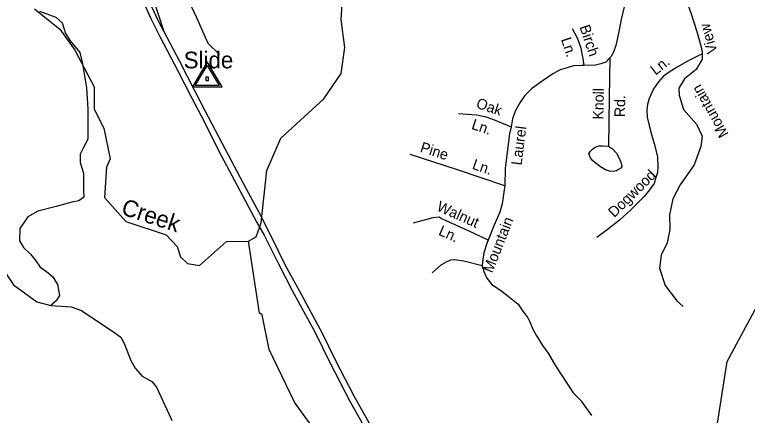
# Model space of a CAD drawing. Extents: x 990631 to 1056237, y 535999 to 585651.
# Drawn here: x 1042549 to 1049136, y 551391 to 554992 of the extents above; entities that cross this region are included whole.
import ezdxf

# ---------------------------------------------------------------- set-up
doc = ezdxf.new("R2010")
doc.units = 0
for name, color, linetype in [('Exist Hydrographic Creek Single Shore', 7, 'Continuous'), ('Exist Hydrographic Creek Single Shore Label', 7, 'Continuous'), ('Exist Road Non-System Type 51', 7, 'Continuous'), ('Exist Road Non-System Type 51 Label', 7, 'Continuous'), ('Exist Road Primary Interstate Divided Center Attributed', 7, 'Continuous'), ('Exist Road Primary Interstate Ramp 1 Lane Attributed', 7, 'Continuous'), ('Exist Survey Geodetic Marker CELL', 7, 'Continuous'), ('Exist Survey Geodetic Marker Label', 7, 'Continuous')]:
    doc.layers.add(name, color=color, linetype=linetype)

msp = doc.modelspace()

# ---------------------------------------------------------------- linework, layer by layer
at = {"layer": 'Exist Hydrographic Creek Single Shore'}
for points in [[(1044652.4, 552955.3), (1044720.5, 552996.7), (1044766.1, 553120.5), (1044814.6, 553592.1), (1044940.6, 553881.6), (1045327.2, 554234.9), (1045484.6, 554464.7), (1045517.2, 554697.1), (1045483.5, 554947.2), (1045500.9, 555229.1), (1045581.2, 555527.7)], [(1042726.7, 555045.3), (1042954.2, 554860.3), (1043089.7, 554673.8), (1043262.7, 554342.1), (1043264.4, 554141.8), (1043350.8, 553972.7), (1043408.7, 553695.9), (1043372.9, 553621.1), (1043355.6, 553349.1), (1043549.1, 553131.8), (1043912.2, 553013), (1044008.8, 552909.3), (1044039.2, 552816.8), (1044104, 552756.4), (1044211.7, 552737.8), (1044452.2, 552952.8), (1044652.4, 552955.3)], [(1049445.6, 548500.3), (1049438.6, 548539.9), (1049074.6, 548895.1), (1048962.6, 549041.8), (1048753.5, 549531.7), (1048626.9, 549744.3), (1048588.6, 549843.6), (1048613.7, 550368.2), (1048706.6, 550648.6), (1048756.5, 550923.2), (1048869.5, 551337.8), (1048953.6, 551874.3), (1049308.5, 552530.1), (1049408.5, 553053.3), (1049407.6, 553269.9), (1049534.5, 553858.1), (1049551.5, 553884), (1049619.5, 554181.3)], [(1045564.2, 550006.6), (1045650.1, 550188.5), (1045739.3, 550297.6), (1045779, 550337.3), (1045934.3, 550370.3), (1045997.1, 550446.4), (1045763.4, 550678.3), (1045669.3, 550864), (1045589.4, 550973.9), (1045304.2, 551176.5), (1045064.8, 551509.6), (1044837.9, 551983.4), (1044773.1, 552293.3), (1044748.6, 552310.1), (1044652.4, 552955.3)]]:
    msp.add_lwpolyline(points, dxfattribs=at)
at = {"layer": 'Exist Road Non-System Type 51'}
for points in [[(1047140.8, 557891.9), (1047023.8, 557816.6), (1046885.8, 557666.1), (1046768.8, 557469.5), (1046693.6, 557268.8), (1046551.4, 556863.1), (1046430.2, 556599.7), (1046359.1, 556553.7), (1046254.6, 556570.4), (1046062.3, 556612.2), (1045673.6, 556720.9), (1045427, 556792), (1045289, 556779.5), (1045071.6, 556683.3), (1044917, 556587.1), (1044565.8, 556281.8), (1044361, 556068.6), (1044269.9, 555844.4), (1044127.8, 555656.2), (1044098.5, 555543.3), (1044090.1, 555166.9), (1044182.1, 554966.2), (1044286.6, 554737.4), (1044391.1, 554632.9)], [(1048561.7, 555408.4), (1048543.3, 555399), (1048503.3, 555398.2), (1048435.7, 555410.4), (1048366.2, 555428.8), (1048296.7, 555443), (1048246.9, 555452.6), (1048220.8, 555449.3), (1048193.9, 555424.3), (1048162.4, 555379.3), (1048128.4, 555314.3), (1048085.3, 555217.6), (1048028.1, 555061.3), (1048002.6, 554948.1), (1047978.5, 554824.8), (1047953.1, 554715.4), (1047933.1, 554656), (1047909.6, 554612.7), (1047899.4, 554603.1)], [(1048561.7, 555408.4), (1048574.1, 555300), (1048575.7, 555217.9), (1048579.8, 555165.8), (1048595.7, 555099), (1048626.9, 555010), (1048681.5, 554842.2), (1048717.5, 554710.8), (1048729.6, 554656.6), (1048731.1, 554640.6)], [(1042771.9, 555023.7), (1042918.2, 554969.4), (1042976.7, 554919.2), (1043006, 554823), (1043047.8, 554756.1), (1043134.4, 554650.8), (1043159.5, 554550.5), (1043193, 554333), (1043205.5, 554144.8), (1043205.5, 553873), (1043163.7, 553793.5), (1043138.6, 553739.2), (1043138.6, 553663.9), (1043167.9, 553567.7), (1043167.9, 553502), (1043167.9, 553418.4), (1043172, 553351.5), (1043126.1, 553318), (1043063.4, 553305.5), (1042921.2, 553267.9), (1042758.2, 553226), (1042666.2, 553175.9), (1042595.2, 553071.3), (1042591, 552960.9), (1042628.6, 552898.2), (1042691.3, 552839.6), (1042733.1, 552789.4), (1042779.1, 552722.5), (1042833.5, 552684.9), (1042892, 552634.7), (1042933.8, 552567.8), (1042950.5, 552467.4), (1042921.2, 552421.4), (1042875.3, 552379.6)], [(1047559.7, 554868.2), (1047603.1, 554788.7), (1047619.8, 554744.2), (1047637.9, 554689.6), (1047648.5, 554641.1), (1047657, 554596.8), (1047667, 554536.5)], [(1047899.4, 554603.1), (1047862.3, 554566.2), (1047817.7, 554549.7), (1047771.3, 554539.2), (1047667, 554536.5)], [(1048731.1, 554640.6), (1048604.9, 554576.5), (1048505.2, 554519.7), (1048431.7, 554475.9), (1048380.4, 554435.5), (1048336.9, 554389), (1048292.8, 554326.3), (1048254, 554239.4), (1048238.3, 554185.9), (1048232.7, 554136.2), (1048236.6, 554069.9), (1048252.1, 553995.4), (1048275.5, 553914.7), (1048304.3, 553813.6), (1048327, 553712.7), (1048332.3, 553628.6), (1048326.6, 553572.7), (1048313.1, 553527.2), (1048299.5, 553475.4), (1048255.7, 553418.9), (1048207.7, 553358.4), (1048083.8, 553236.3), (1047986.7, 553145.4), (1047875.9, 553056.8), (1047781.5, 552987.9)], [(1047899.4, 554603.1), (1047894.1, 554249.1), (1047886.1, 553811.1)], [(1048731.1, 554640.6), (1048729.8, 554592.4), (1048675.2, 554499.9), (1048570.1, 554415.8), (1048519.7, 554331.7), (1048523.9, 554268.7), (1048561.7, 554138.4), (1048679.4, 554008.1), (1048729.8, 553898.8), (1048717.2, 553806.3), (1048658.4, 553642.3), (1048532.3, 553461.6), (1048465.1, 553335.5), (1048435.7, 553192.6), (1048439.9, 553062.3), (1048414.6, 552940.4), (1048360, 552831.1), (1048347.4, 552713.4), (1048397.8, 552559.1), (1048502.9, 552420.4), (1048557.5, 552369.9)], [(1047667, 554536.5), (1047647, 554535.1), (1047572.9, 554531.6), (1047516.3, 554515.4), (1047453.7, 554495.2), (1047386.4, 554459.4), (1047290.2, 554394.5), (1047194, 554325.6), (1047136, 554265.3), (1047090.1, 554200.8), (1047049.5, 554124), (1047025.3, 554054.7), (1047011, 553983.1)], [(1046538.5, 554102.5), (1046702.1, 554091.2), (1046775.8, 554076.7), (1046854.9, 554050.1), (1047011, 553983.1)], [(1042136.5, 553923.9), (1042199.2, 553798.4), (1042203.4, 553664.6), (1042182.5, 553493.2), (1042182.5, 553338.4), (1042195, 553271.5), (1042228.5, 553187.9), (1042333, 553029), (1042429.1, 552725.8), (1042537.8, 552562.7), (1042746.8, 552412.1), (1042875.3, 552379.6)], [(1047011, 553983.1), (1046997, 553919.6), (1046972.8, 553732.2), (1046958.9, 553608.7), (1046954, 553454.7)], [(1047886.1, 553811.1), (1047923.2, 553787.7), (1047958, 553746.6), (1047982.5, 553701.9), (1048001.2, 553657.3), (1048008.2, 553628.9), (1047997.7, 553613.3), (1047977.3, 553599.9), (1047958.8, 553588.5), (1047930.7, 553581.5), (1047896.7, 553584.6), (1047861.2, 553597.7), (1047815.9, 553623.2), (1047780.8, 553652.3), (1047745.8, 553679.4), (1047724.5, 553706.1), (1047711.6, 553740.5), (1047724.5, 553766.1), (1047743.1, 553783.5), (1047767.6, 553800.8), (1047801.9, 553811.8), (1047834.1, 553814.7), (1047886.1, 553811.1)], [(1046954, 553454.7), (1046530.3, 553598.3), (1046104.4, 553736.1)], [(1046954, 553454.7), (1046950.8, 553416.7), (1046930.7, 553293.3), (1046910.4, 553217.9), (1046856.3, 553095.5), (1046806.1, 552965.1)], [(1046806.1, 552965.1), (1046737.1, 552997.3), (1046603.1, 553061.6), (1046429.4, 553139.1), (1046384.1, 553160.7), (1046364.5, 553171.3), (1046308.3, 553165.2), (1046132.7, 553118.7)], [(1046806.1, 552965.1), (1046797.4, 552943.3), (1046766.5, 552850.2), (1046758.5, 552790.4), (1046752.9, 552738.7)], [(1046302.4, 552670.9), (1046382.8, 552742.5), (1046423.6, 552769.1), (1046470.2, 552787.6), (1046502.5, 552792.5), (1046586.1, 552780.1), (1046752.9, 552738.7)], [(1046752.9, 552738.7), (1046752.8, 552734.7), (1046767.2, 552684.2), (1046793.2, 552625.2), (1046839.5, 552567.7), (1046915.8, 552515.1), (1046999.8, 552450.4), (1047074, 552390.1), (1047115.9, 552326.6), (1047161.9, 552267.1), (1047178.8, 552230.5), (1047208.7, 552165.5), (1047237, 552110.7), (1047294.2, 552018.7), (1047346, 551951.1), (1047412.3, 551834.9), (1047568.7, 551593.6)], [(1042875.3, 552379.6), (1043056.1, 552366.1), (1043148.1, 552332.7), (1043315.3, 552223.9), (1043428.2, 552148.7), (1043502.2, 552094.3), (1043535.6, 552031.6), (1043594.1, 551885.2), (1043631.7, 551814.1), (1043694.5, 551743), (1043782.2, 551694.5), (1043824, 551644.3), (1043936.9, 551397.6), (1043962, 551343.2)], [(1047738.8, 551388.3), (1047646.4, 551514.4), (1047568.7, 551593.6)]]:
    msp.add_lwpolyline(points, dxfattribs=at)
at = {"layer": 'Exist Road Primary Interstate Divided Center Attributed'}
for points in [[(1043892.8, 554836.9), (1043844.7, 554927.4), (1043781.8, 555062.7), (1043698.7, 555259.7), (1043614.3, 555480.8), (1043556.7, 555640.3), (1043493.8, 555838.6), (1043438.9, 556038.3), (1043397.3, 556225.9), (1043358.5, 556437.6), (1043344.5, 556534.7)], [(1043651.8, 555227.6), (1043772.4, 554958.2), (1043858.1, 554789.4), (1044012.2, 554494.5), (1044138.1, 554248), (1044254.6, 554025.5), (1044381.9, 553772.3), (1044548, 553457.3), (1044726.1, 553125), (1044793.1, 553009.8), (1044913.6, 552763.2), (1045043.6, 552512.6), (1045249.8, 552134.7), (1045381.1, 551866.7), (1045566, 551512.9), (1045720, 551235.5)], [(1045776.3, 551250.3), (1045600.8, 551562.5), (1045436, 551881.4), (1045315.5, 552125.3), (1045110.5, 552508.6), (1044984.6, 552736.4), (1044857.4, 552995), (1044746.2, 553214.8), (1044632.3, 553423.8), (1044415.3, 553836.6), (1044260, 554127.4), (1044171.6, 554302.9), (1044033.6, 554572.3), (1043892.8, 554836.9)]]:
    msp.add_lwpolyline(points, dxfattribs=at)
at = {"layer": 'Exist Road Primary Interstate Ramp 1 Lane Attributed'}
msp.add_lwpolyline([(1043892.8, 554836.9), (1043780.7, 555178)], dxfattribs=at)
at = {"layer": 'Exist Survey Geodetic Marker CELL'}
for points in [[(1044414.1, 554342.5), (1044280.2, 554568.5), (1044146.7, 554342.5)], [(1044388.2, 554354.6), (1044172.7, 554354.6), (1044280.2, 554536.7)], [(1044292.5, 554401.2), (1044292.5, 554429.4), (1044268.2, 554429.4), (1044268.2, 554401.2)]]:
    msp.add_lwpolyline(points, close=True, dxfattribs=at)

# ---------------------------------------------------------------- texts
at = {"layer": 'Exist Hydrographic Creek Single Shore Label'}
msp.add_text('Creek', height=150, rotation=341.86891, dxfattribs=at).set_placement((1043497.7, 553200.5))
at = {"layer": 'Exist Road Non-System Type 51 Label'}
for s, rotation, p in [('Birch', 288.35174, (1047625.6, 554883)), ('View', 105.31056, (1048867.9, 554656.2)), ('Ln.', 288.35174, (1047459.2, 554770.1)), ('Ln.', 38.24758, (1048310.5, 554443.1)), ('Knoll', 88.95003, (1047841.2, 554048.3)), ('Mountain', 119.52187, (1048970.5, 553919.4)), ('Rd.', 88.95003, (1048035.1, 554070.4)), ('Oak', 341.40993, (1046690.3, 554157.4)), ('Ln.', 341.40993, (1046648.9, 553967.2)), ('Laurel', 82.64619, (1047105.5, 553634.2)), ('Pine', 342.07052, (1046187.1, 553761)), ('Ln.', 341.27778, (1046655.5, 553607.8)), ('Dogwood', 44.59186, (1047940.2, 553163.8)), ('Walnut', 335.94763, (1046335.6, 553234.9)), ('Mountain', 68.40484, (1046842.2, 552664.6)), ('Ln.', 335.94763, (1046351.9, 553015.8))]:
    msp.add_text(s, height=95, rotation=rotation, dxfattribs=at).set_placement(p)
at = {"layer": 'Exist Survey Geodetic Marker Label'}
msp.add_text('Slide', height=150, dxfattribs=at).set_placement((1044068.3, 554509.5))

doc.saveas('drawing.dxf')
